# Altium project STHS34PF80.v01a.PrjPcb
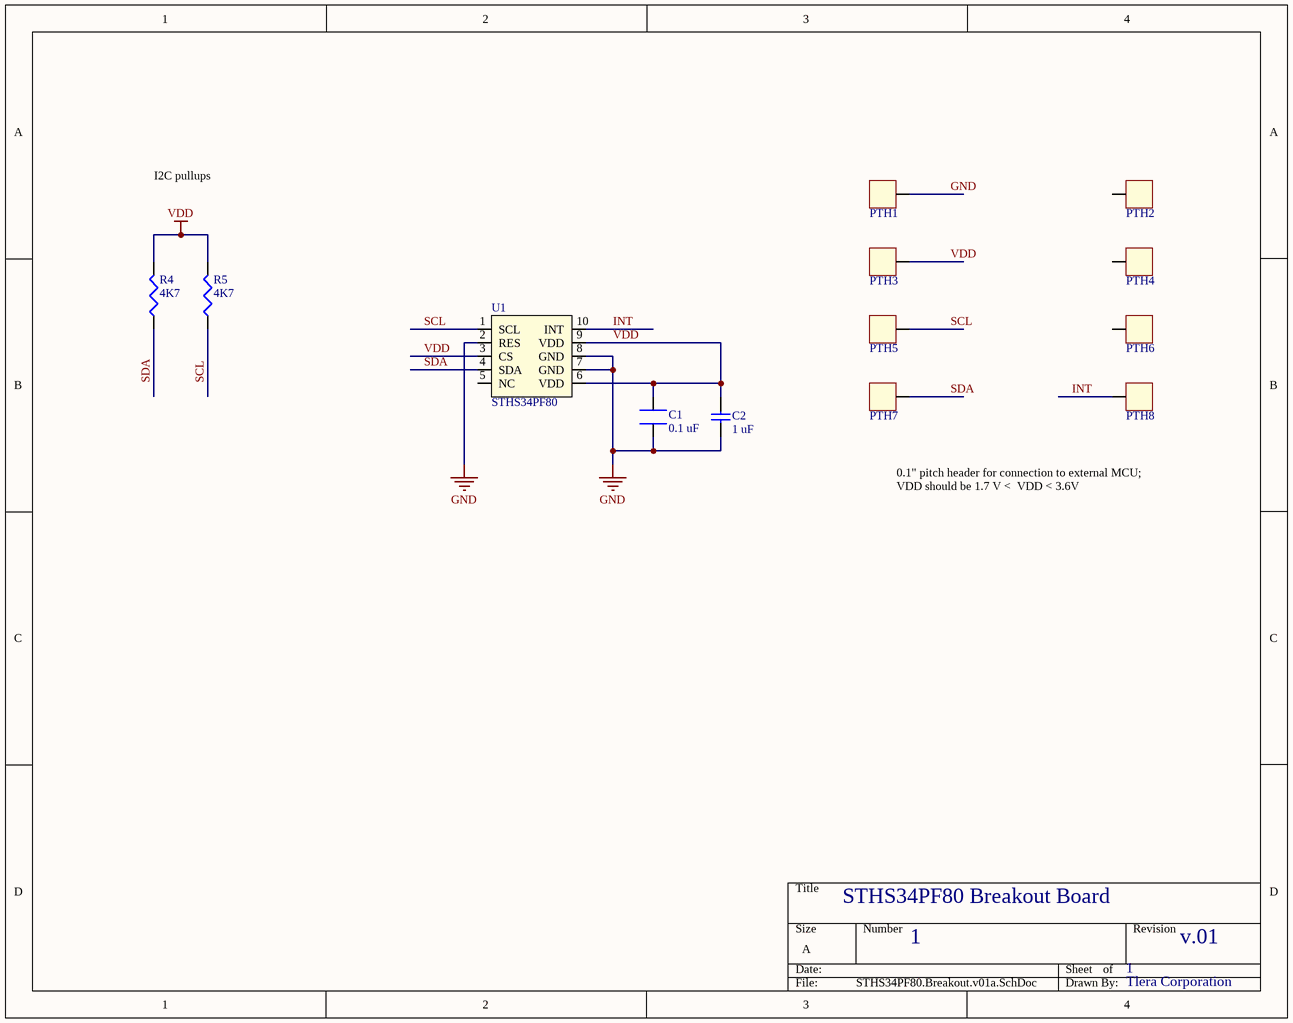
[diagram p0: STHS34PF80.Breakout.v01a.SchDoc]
1 sheet, 13 parts. Net scope: global (net labels, ports and power ports of the same name join across sheets).
Board file: STHS34PF80.Breakout.v01a.PcbDoc

## Sheet STHS34PF80.Breakout.v01a.SchDoc
size A; SheetNumber: 1; SheetTotal: 1

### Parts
C1  0.1 uF  [402Cap]
C2  1 uF  [402Cap]
PTH1  PTH2.54  [PTH2.54]  (value not drawn)
PTH2  PTH2.54  [PTH2.54]  (value not drawn)
PTH3  PTH2.54  [PTH2.54]  (value not drawn)
PTH4  PTH2.54  [PTH2.54]  (value not drawn)
PTH5  PTH2.54  [PTH2.54]  (value not drawn)
PTH6  PTH2.54  [PTH2.54]  (value not drawn)
PTH7  PTH2.54  [PTH2.54]  (value not drawn)
PTH8  PTH2.54  [PTH2.54]  (value not drawn)
R4  4K7  [402RES]
R5  4K7  [402RES]
U1  STHS34PF80  [STHS34PF80TR]

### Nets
GND: C1.1 C2.1 PTH1.1 U1.2(RES) U1.7(GND) U1.8(GND)
VDD: C1.2 C2.2 PTH3.1 R4.2 R5.2 U1.3(CS) U1.6(VDD) U1.9(VDD)
INT: PTH8.1 U1.10(INT)
SCL: PTH5.1 R5.1 U1.1(SCL)
SDA: PTH7.1 R4.1 U1.4(SDA)

Not connected (* = marked no-connect by the designer): PTH2 1; PTH4 1; PTH6 1; U1 5(NC)

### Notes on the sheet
- I2C pullups
- 0.1" pitch header for connection to external MCU; VDD should be 1.7 V <  VDD < 3.6V
- STHS34PF80 Breakout Board
- 1
- v.01
- Tlera Corporation

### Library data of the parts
C1 = CL05B104KO5NNNC: 0402 0.1 uF Ceramic Capacitor, Multilayer, Ceramic, 16V, 10% +Tol, 10% -Tol, X7R, 15% TC, 0.1uF, Surface Mount, 0402; Manufacturer: Samsung; Capacitance: 100nF; Multilayer: Yes
C2 = GRT155R61C105KE01D: 0402 1 uF Ceramic Capacitor, Multilayer, Ceramic, 16V, 10% +Tol, 10% -Tol, X5R, 15% TC, 1uF, Surface Mount, 0402; Manufacturer: Murata; Multilayer: Yes; Reference Standard: AEC-Q200
PTH1-PTH8 = PTH2.54: Standard 0.1" plated through hole for pin headers
R4 R5 = RC0402FR-074K7P: 0402 4K7 Fixed Resistor, Metal Glaze/thick Film, 0.0625W, 4700ohm, 50V, 1% +/-Tol, 150ppm/Cel, Surface Mount, 0402; Manufacturer: Yageo; Additional Feature: LASER TRIMMABLE; Rated Power Dissipation (P): 62.5mW; Rated Temperature: 70°C; Resistance: 4.7kR; Temperature Coefficient: 150ppm/°C
U1 = STHS34PF80: Infrared Detectors Low-power, high-sensitivity infrared sensor for presence and motion detection; Manufacturer: STMicroelectronics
